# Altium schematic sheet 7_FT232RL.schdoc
size 429 x 307 mm; Symbol: Drawing-Symbol_A4; Device: Drawing-Symbol_A4; @Project Name: Slowpoke; @Page Count: 7; @Update Date: 2025-12-15; @Create Date: 2025-12-13; @Schematic Name: Slowpoke_Sch; @Page No: 7; @Page Name: FT232RL; Company: Analog Devices, Inc.; Version: V1.0; Page Size: A4; @Create Time: 14:28:30; @Update Time: 16:16:35; Width: 1655; Height: 1170; Region Start: 1; X Region Count: 6; Y Region Count: 4; Blade Width: 10; Title Block Position: 3; @Board Name: Slowpoke
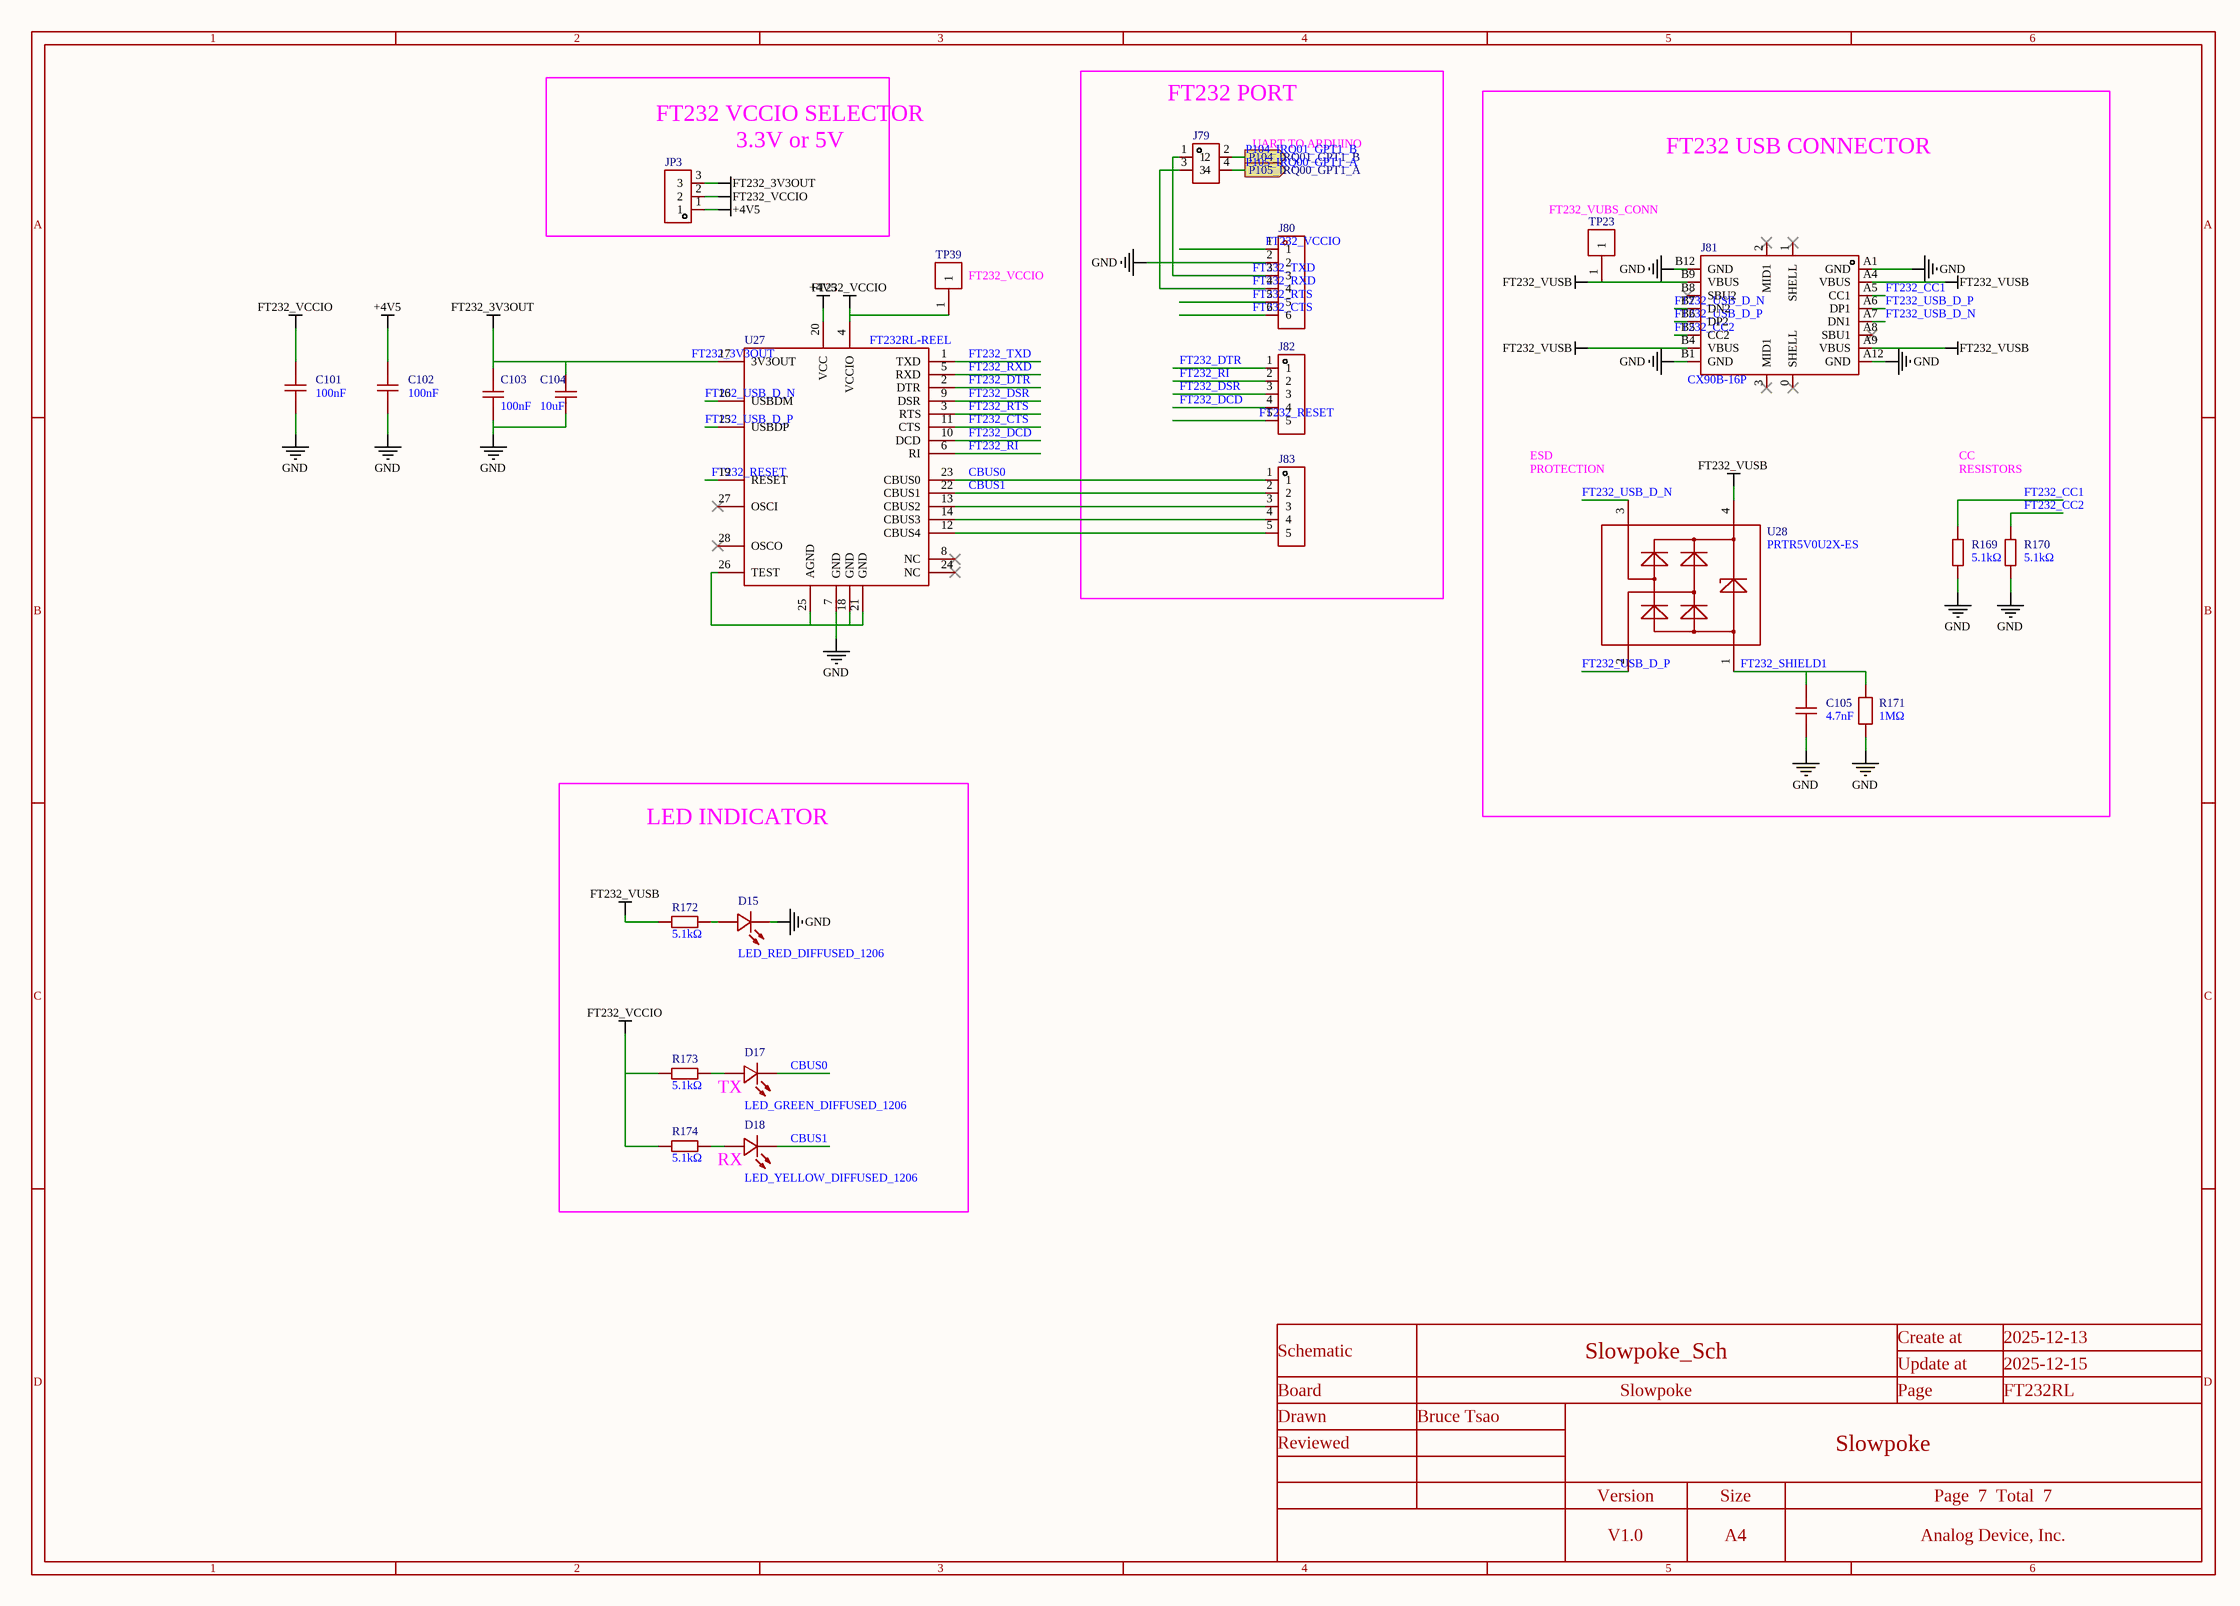
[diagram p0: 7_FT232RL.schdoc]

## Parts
C101  100nF  [C0402]
C102  100nF  [C0402]
C103  100nF  [C0402]
C104  10uF  [C0402]
C105  4.7nF  [C0805]
D15  LED_RED_DIFFUSED_1206  [LED1206-RD]
D17  LED_GREEN_DIFFUSED_1206  [LED1206-RD]
D18  LED_YELLOW_DIFFUSED_1206  [LED1206-RD]
J79  ZX-PZ2.54-2-2PZZ  [HDR-TH_4P-P2.54-V-M-R2-C2-S2.54]  (value not drawn)
J80  2.54-1*6P母  [HDR-TH_6P-P2.54-V-F]  (value not drawn)
J81  CX90B-16P  [USB-C-SMD_CX90B-16P]
J82  PZ254V-11-05P  [HDR-TH_5P-P2.54-V-M]  (value not drawn)
J83  PZ254V-11-05P  [HDR-TH_5P-P2.54-V-M]  (value not drawn)
JP3  PZ254V-11-03P  [HDR-TH_3P-P2.54-V-M]  (value not drawn)
R169  5.1kΩ  [R0402]
R170  5.1kΩ  [R0402]
R171  1MΩ  [R0402]
R172  5.1kΩ  [R0402]
R173  5.1kΩ  [R0402]
R174  5.1kΩ  [R0402]
TP23  RH-5000  [TEST-TH_BD2.54-P1.4_RED]  (value not drawn)
TP39  RH-5000  [TEST-TH_BD2.54-P1.4_RED]  (value not drawn)
U27  FT232RL-REEL  [SSOP-28_L10.2-W5.3-P0.65-LS7.8-BL]
U28  PRTR5V0U2X-ES  [SOT-143_L2.9-W1.3-P1.92-LS2.3-BR]

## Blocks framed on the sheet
FT232 PORT: J79 J80 J82 J83
FT232 USB CONNECTOR: C105 J81 R169-R171 TP23 U28
LED INDICATOR: D15 D17 D18 R172-R174

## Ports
P104_IRQ01_GPT1_B (out), P105_IRQ00_GPT1_A (out)

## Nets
+4V5: C102.1 JP3.1 U27.20(VCC)
FT232_3V3OUT: C103.2 C104.2 JP3.3 U27.17(3V3OUT)
FT232_VCCIO: C101.1 J80.1 JP3.2 R173.2 R174.2 TP39.1 U27.4(VCCIO)
FT232_VUSB: J81.A4(VBUS) J81.A9(VBUS) J81.B4(VBUS) J81.B9(VBUS) R172.2 TP23.1 U28.4(VCC)
GND: C101.2 C102.2 C103.1 C104.1 C105.1 D15.1(K) J80.2 J81.A1(GND) J81.A12(GND) J81.B1(GND) J81.B12(GND) R169.1 R170.1 R171.1 U27.7(GND) U27.18(GND) U27.21(GND) U27.25(AGND) U27.26(TEST)
CBUS0: D17.1(K) J83.1 U27.23(CBUS0)
CBUS1: D18.1(K) J83.2 U27.22(CBUS1)
FT232_CC1: J81.A5(CC1) R169.2
FT232_CC2: J81.B5(CC2) R170.2
FT232_CTS: J80.6 U27.11(CTS)
FT232_DCD: J82.4 U27.10(DCD)
FT232_DSR: J82.3 U27.9(DSR)
FT232_DTR: J82.1 U27.2(DTR)
FT232_RESET: J82.5 U27.19(RESET)
FT232_RI: J82.2 U27.6(RI)
FT232_RTS: J80.5 U27.3(RTS)
FT232_RXD: J79.3 J80.4 U27.5(RXD)
FT232_SHIELD1: C105.2 R171.2 U28.1(GND)
FT232_TXD: J79.1 J80.3 U27.1(TXD)
FT232_USB_D_N: J81.A7(DN1) J81.B7(DN2) U27.16(USBDM) U28.3(IO)
FT232_USB_D_P: J81.A6(DP1) J81.B6(DP2) U27.15(USBDP) U28.2(IO)
P104_IRQ01_GPT1_B: J79.2 ; port P104_IRQ01_GPT1_B
P105_IRQ00_GPT1_A: J79.4 ; port P105_IRQ00_GPT1_A
NetD15_2: D15.2(A) R172.1
NetD17_2: D17.2(A) R173.1
NetD18_2: D18.2(A) R174.1
NetJ83_3: J83.3 U27.13(CBUS2)
NetJ83_4: J83.4 U27.14(CBUS3)
NetJ83_5: J83.5 U27.12(CBUS4)

Not connected (* = marked no-connect by the designer): J81 0(SHELL)* 1(SHELL)* 2(MID1)* 3(MID1)* A8(SBU1)* B8(SBU2)*; U27 8(NC)* 24(NC)* 27(OSCI)* 28(OSCO)*

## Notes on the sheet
- (near JP3) FT232 VCCIO SELECTOR
  3.3V or 5V
- (near J79) UART TO ARDUINO
- (near TP23) FT232_VUBS_CONN
- (near TP39) FT232_VCCIO
- (near U28) ESD
  PROTECTION
- CC
  RESISTORS
- (near D17) TX
- (near D18) RX

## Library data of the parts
C101-C103 = GRM155R61H104KE19D: Manufacturer: muRata(村田); Add into BOM: yes; Tolerance: ±10%
C104 = CL05A105KP5NNNC: Manufacturer: SAMSUNG(三星); Add into BOM: yes; Tolerance: ±10%; Voltage Rating: 10V; Temperature Coefficient: X5R
C105 = FV21X472K102ECG: Manufacturer: PSA(信昌电陶); Add into BOM: yes; Tolerance: ±10%; Voltage Rating: 1kV; Temperature Coefficient: X7R
D15 D17 D18 = LTST-C150KRKT: Manufacturer: LITEON(光宝); Add into BOM: yes; Emitted Color: Red; Forward Voltage (VF): 2V; Power Dissipation: 62.5mW; Forward Current: 20mA; Dominant Wavelength: 624nm; Peak Wavelength: 639nm; Lens Color: 无色透明透镜; Luminous Intensity: 54mcd; Viewing Angle: 130°
J79 = ZX-PZ2.54-2-2PZZ: Manufacturer: Megastar(兆星); Add into BOM: yes; Pin Structure: 2x2P; Pitch: 2.54mm; Circluar Pins/Square Pins: Policy; Current Rating: 3A; Voltage Rating (Max): 1kV
J80 = 2.54-1*6P母: Manufacturer: BOOMELE(博穆精密); Symbol: Header-Female-2.54_1x6; Add into BOM: yes; Holes Structure: 1x6P; Pitch: 2.54mm; Circular Hole / Square Hole: Square Hole; Number of Positions: 6P; Current Rating: 3A; Holes Direction: Top
J81 = CX90B-16P: Manufacturer: HRS(广濑); Add into BOM: yes
J82 J83 = PZ254V-11-05P: Manufacturer: XFCN(兴飞); Add into BOM: yes; Pin Structure: 1x5P; Pitch: 2.54mm; Circluar Pins/Square Pins: Policy
JP3 = PZ254V-11-03P: Manufacturer: XFCN(兴飞); Symbol: PZ254V-11-03P_C2937625; Add into BOM: yes; Pin Structure: 1x3P; Pitch: 2.54mm; Circluar Pins/Square Pins: Pin Header; Current Rating: 3A; Voltage Rating (Max): 250V
R169 R170 R172-R174 = RC0402FR-075K1L: Manufacturer: YAGEO(国巨); Add into BOM: yes; Tolerance: ±1%; Power(Watts): 62.5mW; Voltage-Supply(Max): 50V; Temperature Coefficient: ±100ppm/℃
R171 = CRCW04021M00FKED: Manufacturer: VISHAY(威世); Add into BOM: yes; Tolerance: ±1%; Power(Watts): 63mW; Voltage-Supply(Max): 50V; Temperature Coefficient: ±100ppm/℃
TP23 TP39 = RH-5000: Manufacturer: 荣和; Add into BOM: yes; Connector Type: Pin Type (Through-Board); Plastic Color: Red; Board Space (Diameter φ/ Length x Width): 2.5mm
U27 = FT232RL-REEL: Manufacturer: FTDI(飞特帝亚); Add into BOM: yes; Applications Function: USB to UART; USB Protocol: USB 2.0; Voltage - Supply: 3.3V~5.25V; Data Rate: 3Mbps; Current - Supply: 15mA; Supply Current (Iq): 70uA
U28 = PRTR5V0U2X-ES: Manufacturer: ElecSuper(静芯); Add into BOM: yes; Polarity: Unidirectional; Reverse Stand-Off Voltage (Vrwm): 5V; Clamping Voltage: 18V; Peak Pulse Current (Ipp): 9A@8/20us; Peak Pulse Power Dissipation (Ppp): 180W@8/20us; Voltage - Breakdown: 6V; Reverse Leakage Current (Ir): 1uA; Number of Channels: 2; level of protection: IEC 61000-4-2；IEC 61000-4-4；IEC 61000-4-5; Junction Capacitance: 0.8pF；1.6pF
